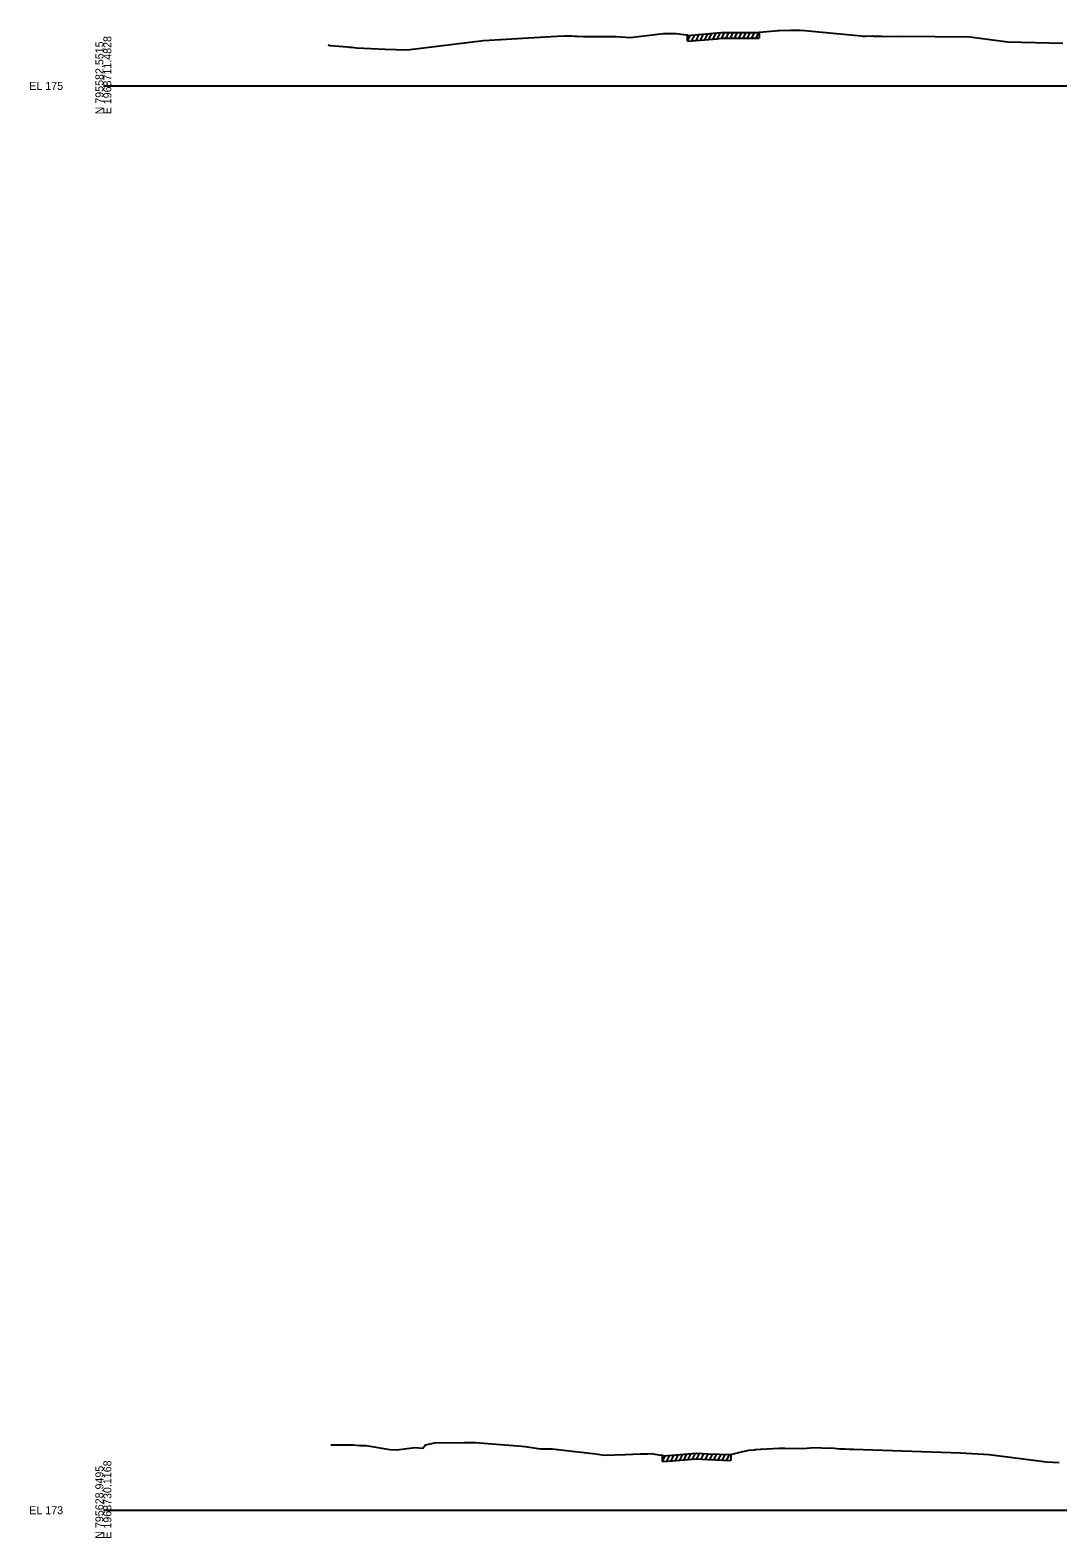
# Model space of a CAD drawing. Extents: x 1017 to 19997, y -1947 to 50737.
# Drawn here: x 15974 to 16335, y 8990 to 9520 of the extents above; entities that cross this region are included whole.
import ezdxf

# ---------------------------------------------------------------- set-up
doc = ezdxf.new("R2010")
doc.units = 0
for name, color, linetype in [('RD_GPK_XS_Cell', 7, 'Continuous'), ('RD_XS_ExGround', 7, 'Continuous'), ('RD_XS_ExPaveRet', 7, 'Continuous')]:
    doc.layers.add(name, color=color, linetype=linetype)

msp = doc.modelspace()

# ---------------------------------------------------------------- linework, layer by layer
at = {"layer": 'RD_GPK_XS_Cell'}
for p, q in [((16000, 9500), (16600, 9500)), ((16000, 9000), (16600, 9000))]:
    msp.add_line(p, q, dxfattribs=at)
at = {"layer": 'RD_XS_ExGround'}
for points in [[(16078.87, 9514.42), (16079.62, 9514.15), (16085.71, 9513.68), (16086.39, 9513.64), (16087.14, 9513.57), (16088.77, 9513.34), (16098.84, 9512.86), (16106.6, 9512.66), (16133.41, 9515.94), (16159.1, 9517.48), (16161.76, 9517.55), (16164.32, 9517.51), (16165.41, 9517.46), (16166.31, 9517.4), (16168.48, 9517.31), (16179.95, 9517.38), (16184.8, 9517.02), (16196.58, 9518.37), (16197.02, 9518.36), (16198.97, 9518.39), (16200.98, 9518.42), (16204.58, 9517.97), (16204.91, 9517.94), (16205.01, 9517.74), (16215.43, 9518.57), (16216.78, 9518.7), (16226.37, 9518.72), (16230.13, 9518.74), (16230.24, 9518.83), (16236.79, 9519.42), (16237.17, 9519.43), (16241.07, 9519.56), (16244.51, 9519.54), (16246.15, 9519.47), (16264.79, 9517.65), (16265.77, 9517.57), (16266.54, 9517.46), (16267.36, 9517.48), (16269.72, 9517.51), (16270.38, 9517.49), (16272.12, 9517.44), (16273.15, 9517.4), (16273.89, 9517.36), (16279.73, 9517.45), (16304.06, 9517.21), (16317.42, 9515.46), (16336.68, 9514.96)], [(16079.77, 9022.92), (16080.3, 9022.91), (16080.67, 9022.94), (16082.46, 9023), (16083.4, 9022.94), (16087.8, 9022.92), (16089.9, 9022.68), (16092.23, 9022.71), (16100.47, 9021.36), (16102.93, 9021.21), (16109.35, 9022.07), (16112.04, 9021.76), (16113, 9022.98), (16116.33, 9023.61), (16126.51, 9023.81), (16130.49, 9023.81), (16146.83, 9022.53), (16147.96, 9022.36), (16153.37, 9021.57), (16153.88, 9021.57), (16157.52, 9021.59), (16161.44, 9021.08), (16172.75, 9019.76), (16175.69, 9019.31), (16183.22, 9019.53), (16188.34, 9019.84), (16190.97, 9019.85), (16192.17, 9019.86), (16194.98, 9019.47), (16196.15, 9019.34), (16196.25, 9019.14), (16199.6, 9019.36), (16207.96, 9020.02), (16212.18, 9019.77), (16220.19, 9019.51), (16223.94, 9020.46), (16226.47, 9021.09), (16228.43, 9021.19), (16228.8, 9021.29), (16230.43, 9021.41), (16230.8, 9021.44), (16237.18, 9021.73), (16239.16, 9021.78), (16243.37, 9021.65), (16246.8, 9021.78), (16248, 9021.86), (16251.12, 9022.06), (16252.9, 9021.77), (16255.33, 9021.85), (16258.46, 9021.5), (16260.27, 9021.51), (16261.73, 9021.48), (16263.27, 9021.48), (16300.74, 9020.1), (16310.87, 9019.54), (16330.89, 9017.01), (16335.38, 9016.75)]]:
    msp.add_lwpolyline(points, dxfattribs=at)
at = {"layer": 'RD_XS_ExPaveRet'}
for p, q in [((16205.01, 9515.74), (16206.05, 9517.82)), ((16205.01, 9515.74), (16205.01, 9517.74)), ((16205.01, 9515.74), (16215.43, 9516.57)), ((16206.51, 9515.86), (16207.55, 9517.94)), ((16208.01, 9515.98), (16209.05, 9518.06)), ((16209.51, 9516.1), (16210.55, 9518.18)), ((16211.01, 9516.22), (16212.05, 9518.3)), ((16212.51, 9516.34), (16213.55, 9518.42)), ((16214.01, 9516.46), (16215.05, 9518.54)), ((16215.43, 9516.57), (16216.78, 9516.7)), ((16215.51, 9516.58), (16216.56, 9518.68)), ((16216.78, 9516.7), (16226.37, 9516.72)), ((16217.01, 9516.7), (16218.01, 9518.7)), ((16218.51, 9516.7), (16219.51, 9518.7)), ((16220.01, 9516.7), (16221.01, 9518.71)), ((16221.51, 9516.71), (16222.51, 9518.71)), ((16223.01, 9516.71), (16224.01, 9518.71)), ((16224.51, 9516.71), (16225.51, 9518.72)), ((16226.01, 9516.72), (16227.01, 9518.72)), ((16226.37, 9516.72), (16230.13, 9516.74)), ((16227.51, 9516.72), (16228.52, 9518.73)), ((16229.01, 9516.73), (16230.02, 9518.74)), ((16230.13, 9518.74), (16230.13, 9516.74)), ((16196.25, 9017.14), (16197.28, 9019.21)), ((16196.25, 9017.14), (16196.25, 9019.14)), ((16197.75, 9017.24), (16198.78, 9019.3)), ((16199.25, 9017.33), (16200.29, 9019.41)), ((16200.75, 9017.45), (16201.79, 9019.53)), ((16202.25, 9017.57), (16203.29, 9019.65)), ((16203.75, 9017.68), (16204.79, 9019.77)), ((16205.25, 9017.8), (16206.29, 9019.88)), ((16206.75, 9017.92), (16207.79, 9020)), ((16208.25, 9018), (16209.22, 9019.94)), ((16209.75, 9017.91), (16210.72, 9019.85)), ((16211.25, 9017.82), (16212.22, 9019.77)), ((16212.75, 9017.75), (16213.73, 9019.72)), ((16214.25, 9017.7), (16215.23, 9019.67)), ((16215.75, 9017.65), (16216.73, 9019.62)), ((16217.25, 9017.6), (16218.23, 9019.57)), ((16218.75, 9017.55), (16219.73, 9019.52)), ((16220.19, 9019.51), (16220.19, 9017.51)), ((16196.25, 9017.14), (16199.6, 9017.36)), ((16199.6, 9017.36), (16207.96, 9018.02)), ((16207.96, 9018.02), (16212.18, 9017.77)), ((16212.18, 9017.77), (16220.19, 9017.51))]:
    msp.add_line(p, q, dxfattribs=at)

# ---------------------------------------------------------------- texts
at = {"layer": 'RD_GPK_XS_Cell'}
for s, p in [('E 1968711.4828', (16002.8, 9490)), ('N 795582.5515', (16000, 9490)), ('N 795628.9495', (16000, 8990)), ('E 1968730.1168', (16002.8, 8990))]:
    msp.add_text(s, height=2.8, rotation=90, dxfattribs=at).set_placement(p)
for s, p in [('EL 175', (15974, 9498.6)), ('EL 173', (15974, 8998.6))]:
    msp.add_text(s, height=2.8, dxfattribs=at).set_placement(p)

doc.saveas('drawing.dxf')
